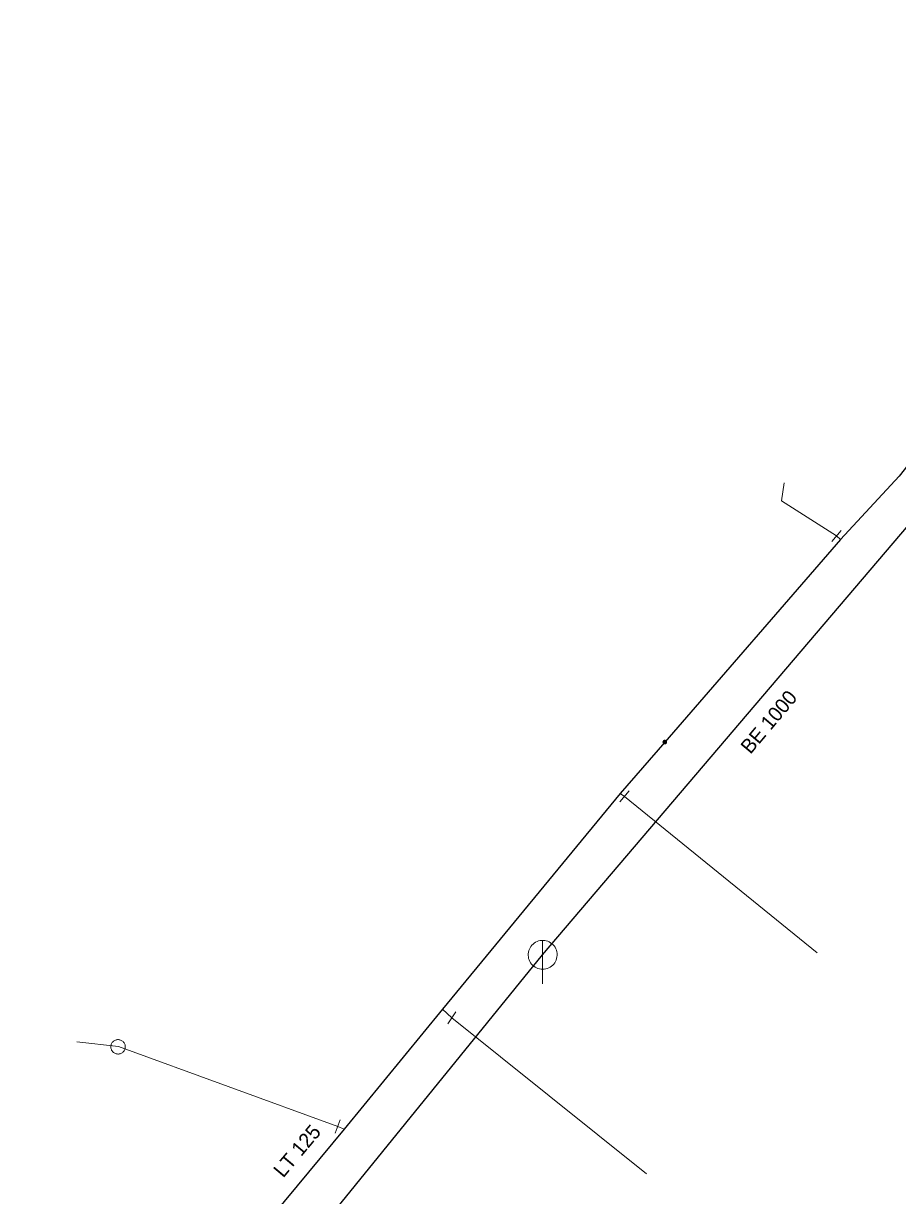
# Model space of a CAD drawing. Extents: x -791337 to -790755, y -988454 to -987923.
# Drawn here: x -791010.1 to -790949.7, y -988277.2 to -988196.2 of the extents above; entities that cross this region are included whole.
import ezdxf

# ---------------------------------------------------------------- set-up
doc = ezdxf.new("R2010")
doc.units = 0
doc.header["$LTSCALE"] = 0.4
for name, color, linetype, lineweight in [('1', 7, 'Continuous', 13), ('13', 7, 'Continuous', 13), ('14', 7, 'Continuous', 25), ('17', 7, 'Continuous', 25), ('22', 7, 'Continuous', 13), ('23', 7, 'Continuous', 13), ('34', 7, 'Continuous', 13), ('9', 7, 'Continuous', 13)]:
    doc.layers.add(name, color=color, linetype=linetype, lineweight=lineweight)

msp = doc.modelspace()

# ---------------------------------------------------------------- linework, layer by layer
at = {"layer": '13'}
for p, q in [((-790968.589, -988249.619), (-790955.254, -988260.441)), ((-790981.155, -988264.329), (-790980.511, -988264.931)), ((-790980.511, -988264.931), (-790967.056, -988275.712))]:
    msp.add_line(p, q, dxfattribs=at)
for points in [[(-790953.929, -988231.608), (-790957.739, -988229.175), (-790957.552, -988227.934)], [(-790988.399, -988272.438), (-791003.556, -988266.918), (-791006.438, -988266.59)]]:
    msp.add_lwpolyline(points, dxfattribs=at)
at = {"layer": '14'}
msp.add_line((-790974.239, -988260.57), (-790944.001, -988225.028), dxfattribs=at)
at = {"layer": '14', "lineweight": 13}
for p, q in [((-790953.649, -988231.855), (-790953.929, -988231.608)), ((-790968.875, -988249.407), (-790968.589, -988249.619)), ((-790987.956, -988272.624), (-790988.399, -988272.438))]:
    msp.add_line(p, q, dxfattribs=at)
at = {"layer": '14'}
msp.add_lwpolyline([(-791005.342, -988298.738), (-790994.723, -988285.809), (-790974.239, -988260.57)], dxfattribs=at)
at = {"layer": '17'}
for points in [[(-790868.789, -988131.909), (-790886.164, -988144.675), (-790899.148, -988162.743), (-790910.179, -988178.094), (-790927.416, -988199.874), (-790939.877, -988215.123), (-790949.601, -988227.486), (-790953.649, -988231.855), (-790965.795, -988245.864)], [(-790965.795, -988245.864), (-790968.875, -988249.407), (-790981.155, -988264.329), (-790987.956, -988272.624), (-790992.881, -988278.57), (-791010.125, -988299.302)]]:
    msp.add_lwpolyline(points, dxfattribs=at)
at = {"layer": '22'}
msp.add_line((-790974.239, -988262.57), (-790974.238, -988259.57), dxfattribs=at)
msp.add_lwpolyline([(-790973.239, -988260.57), (-790973.244, -988260.461), (-790973.262, -988260.353), (-790973.292, -988260.247), (-790973.332, -988260.146), (-790973.384, -988260.049), (-790973.446, -988259.959), (-790973.518, -988259.876), (-790973.598, -988259.802), (-790973.686, -988259.736), (-790973.78, -988259.681), (-790973.88, -988259.636), (-790973.985, -988259.603), (-790974.092, -988259.581), (-790974.201, -988259.571), (-790974.311, -988259.573), (-790974.419, -988259.587), (-790974.526, -988259.612), (-790974.629, -988259.649), (-790974.727, -988259.698), (-790974.819, -988259.756), (-790974.905, -988259.825), (-790974.982, -988259.902), (-790975.051, -988259.988), (-790975.11, -988260.08), (-790975.158, -988260.178), (-790975.195, -988260.281), (-790975.221, -988260.388), (-790975.235, -988260.496), (-790975.238, -988260.606), (-790975.228, -988260.715), (-790975.207, -988260.822), (-790975.173, -988260.926), (-790975.129, -988261.026), (-790975.074, -988261.121), (-790975.008, -988261.209), (-790974.934, -988261.289), (-790974.851, -988261.361), (-790974.761, -988261.423), (-790974.665, -988261.475), (-790974.563, -988261.516), (-790974.458, -988261.546), (-790974.35, -988261.564), (-790974.24, -988261.57), (-790974.131, -988261.564), (-790974.023, -988261.546), (-790973.918, -988261.517), (-790973.816, -988261.476), (-790973.719, -988261.424), (-790973.629, -988261.362), (-790973.546, -988261.291), (-790973.471, -988261.211), (-790973.406, -988261.123), (-790973.35, -988261.029), (-790973.306, -988260.929), (-790973.272, -988260.825), (-790973.25, -988260.717), (-790973.24, -988260.608)], close=True, dxfattribs=at)
at = {"layer": '23'}
for points in [[(-791003.116, -988267.105), (-791003.1, -988267.054), (-791003.09, -988267.002), (-791003.086, -988266.951), (-791003.087, -988266.899), (-791003.093, -988266.847), (-791003.105, -988266.795), (-791003.121, -988266.746), (-791003.143, -988266.699), (-791003.169, -988266.654), (-791003.2, -988266.612), (-791003.236, -988266.573), (-791003.276, -988266.538), (-791003.318, -988266.508), (-791003.363, -988266.483), (-791003.411, -988266.462), (-791003.462, -988266.446), (-791003.512, -988266.436), (-791003.566, -988266.431), (-791003.616, -988266.431), (-791003.669, -988266.437), (-791003.721, -988266.45), (-791003.77, -988266.466), (-791003.818, -988266.488), (-791003.863, -988266.514), (-791003.904, -988266.545), (-791003.943, -988266.582), (-791003.977, -988266.62), (-791004.007, -988266.663), (-791004.033, -988266.709), (-791004.054, -988266.757), (-791004.07, -988266.806), (-791004.08, -988266.858), (-791004.085, -988266.911), (-791004.085, -988266.962), (-791004.078, -988267.013), (-791004.066, -988267.065), (-791004.05, -988267.115), (-791004.028, -988267.163), (-791004.001, -988267.208)], [(-791003.566, -988266.431), (-791003.616, -988266.431), (-791003.669, -988266.437), (-791003.721, -988266.45), (-791003.77, -988266.466), (-791003.818, -988266.488), (-791003.863, -988266.514), (-791003.904, -988266.545), (-791003.943, -988266.582), (-791003.977, -988266.62), (-791004.007, -988266.663), (-791004.033, -988266.709), (-791004.054, -988266.757), (-791004.07, -988266.806), (-791004.08, -988266.858), (-791004.085, -988266.911), (-791004.085, -988266.962), (-791004.078, -988267.013), (-791004.066, -988267.065), (-791004.05, -988267.115), (-791004.028, -988267.163), (-791004.001, -988267.208), (-791003.971, -988267.249), (-791003.934, -988267.288), (-791003.896, -988267.323), (-791003.852, -988267.353), (-791003.807, -988267.377), (-791003.76, -988267.399), (-791003.71, -988267.414), (-791003.658, -988267.425), (-791003.606, -988267.43), (-791003.554, -988267.429), (-791003.501, -988267.423), (-791003.451, -988267.412), (-791003.401, -988267.394), (-791003.354, -988267.374), (-791003.309, -988267.347), (-791003.266, -988267.315), (-791003.227, -988267.28), (-791003.193, -988267.24)], [(-791004.001, -988267.208), (-791003.971, -988267.249), (-791003.934, -988267.288), (-791003.896, -988267.323), (-791003.852, -988267.353), (-791003.807, -988267.377), (-791003.76, -988267.399), (-791003.71, -988267.414), (-791003.658, -988267.425), (-791003.606, -988267.43), (-791003.554, -988267.429), (-791003.501, -988267.423), (-791003.451, -988267.412), (-791003.401, -988267.394), (-791003.354, -988267.374), (-791003.309, -988267.347), (-791003.266, -988267.315), (-791003.227, -988267.28), (-791003.193, -988267.24), (-791003.164, -988267.197), (-791003.138, -988267.152), (-791003.116, -988267.105), (-791003.1, -988267.054), (-791003.09, -988267.002), (-791003.086, -988266.951), (-791003.087, -988266.899), (-791003.093, -988266.847), (-791003.105, -988266.795), (-791003.121, -988266.746), (-791003.143, -988266.699), (-791003.169, -988266.654), (-791003.2, -988266.612), (-791003.236, -988266.573), (-791003.276, -988266.538), (-791003.318, -988266.508), (-791003.363, -988266.483), (-791003.411, -988266.462), (-791003.462, -988266.446), (-791003.512, -988266.436), (-791003.566, -988266.431)], [(-791003.193, -988267.24), (-791003.164, -988267.197), (-791003.138, -988267.152), (-791003.116, -988267.105)]]:
    msp.add_lwpolyline(points, dxfattribs=at)
at = {"layer": '34'}
for p, q in [((-790953.603, -988231.228), (-790954.254, -988231.987)), ((-790968.27, -988249.233), (-790968.907, -988250.004)), ((-790980.24, -988264.51), (-790980.782, -988265.35)), ((-790988.228, -988271.968), (-790988.57, -988272.907))]:
    msp.add_line(p, q, dxfattribs=at)
at = {"layer": '9'}
for points in [[(-790965.921, -988245.864), (-790965.921, -988245.877), (-790965.919, -988245.89), (-790965.916, -988245.903), (-790965.911, -988245.915), (-790965.905, -988245.927), (-790965.898, -988245.938), (-790965.89, -988245.948), (-790965.88, -988245.958), (-790965.87, -988245.966), (-790965.859, -988245.973), (-790965.847, -988245.979), (-790965.835, -988245.984), (-790965.822, -988245.987), (-790965.809, -988245.989), (-790965.796, -988245.991), (-790965.783, -988245.99), (-790965.77, -988245.988), (-790965.757, -988245.985), (-790965.745, -988245.98), (-790965.733, -988245.974), (-790965.722, -988245.967), (-790965.712, -988245.959), (-790965.702, -988245.949), (-790965.694, -988245.939), (-790965.687, -988245.928), (-790965.681, -988245.916), (-790965.676, -988245.904), (-790965.673, -988245.891), (-790965.671, -988245.878), (-790965.669, -988245.865), (-790965.67, -988245.852), (-790965.672, -988245.839), (-790965.675, -988245.826), (-790965.68, -988245.814), (-790965.686, -988245.802), (-790965.693, -988245.791), (-790965.701, -988245.781), (-790965.711, -988245.771), (-790965.721, -988245.763), (-790965.732, -988245.756), (-790965.744, -988245.75), (-790965.756, -988245.745), (-790965.769, -988245.742), (-790965.782, -988245.74), (-790965.795, -988245.739), (-790965.808, -988245.739), (-790965.821, -988245.741), (-790965.834, -988245.744), (-790965.846, -988245.749), (-790965.858, -988245.755), (-790965.869, -988245.762), (-790965.879, -988245.77), (-790965.889, -988245.78), (-790965.897, -988245.79), (-790965.904, -988245.801), (-790965.91, -988245.813), (-790965.915, -988245.825), (-790965.918, -988245.838), (-790965.92, -988245.851)], [(-790965.901, -988245.864), (-790965.902, -988245.875), (-790965.9, -988245.886), (-790965.897, -988245.897), (-790965.893, -988245.907), (-790965.888, -988245.917), (-790965.882, -988245.926), (-790965.875, -988245.935), (-790965.867, -988245.943), (-790965.858, -988245.95), (-790965.849, -988245.956), (-790965.839, -988245.961), (-790965.829, -988245.965), (-790965.818, -988245.968), (-790965.807, -988245.971), (-790965.796, -988245.971), (-790965.785, -988245.971), (-790965.774, -988245.969), (-790965.763, -988245.966), (-790965.753, -988245.962), (-790965.743, -988245.957), (-790965.734, -988245.951), (-790965.725, -988245.944), (-790965.717, -988245.936), (-790965.71, -988245.927), (-790965.704, -988245.918), (-790965.699, -988245.908), (-790965.695, -988245.898), (-790965.692, -988245.887), (-790965.69, -988245.876), (-790965.689, -988245.865), (-790965.689, -988245.854), (-790965.691, -988245.843), (-790965.694, -988245.832), (-790965.698, -988245.822), (-790965.703, -988245.812), (-790965.709, -988245.803), (-790965.716, -988245.794), (-790965.724, -988245.786), (-790965.733, -988245.779), (-790965.742, -988245.773), (-790965.752, -988245.768), (-790965.762, -988245.764), (-790965.773, -988245.761), (-790965.784, -988245.759), (-790965.795, -988245.759), (-790965.806, -988245.758), (-790965.817, -988245.76), (-790965.828, -988245.763), (-790965.838, -988245.767), (-790965.848, -988245.772), (-790965.857, -988245.778), (-790965.866, -988245.785), (-790965.874, -988245.793), (-790965.881, -988245.802), (-790965.887, -988245.811), (-790965.892, -988245.821), (-790965.896, -988245.831), (-790965.899, -988245.842), (-790965.901, -988245.853)], [(-790965.882, -988245.864), (-790965.882, -988245.873), (-790965.881, -988245.882), (-790965.878, -988245.891), (-790965.875, -988245.899), (-790965.871, -988245.907), (-790965.866, -988245.915), (-790965.86, -988245.922), (-790965.854, -988245.928), (-790965.847, -988245.934), (-790965.839, -988245.939), (-790965.831, -988245.943), (-790965.823, -988245.946), (-790965.814, -988245.949), (-790965.805, -988245.95), (-790965.796, -988245.952), (-790965.787, -988245.951), (-790965.778, -988245.95), (-790965.769, -988245.947), (-790965.761, -988245.944), (-790965.753, -988245.94), (-790965.745, -988245.935), (-790965.738, -988245.929), (-790965.732, -988245.923), (-790965.726, -988245.916), (-790965.721, -988245.908), (-790965.717, -988245.9), (-790965.714, -988245.892), (-790965.711, -988245.883), (-790965.71, -988245.874), (-790965.708, -988245.865), (-790965.709, -988245.856), (-790965.71, -988245.847), (-790965.713, -988245.838), (-790965.716, -988245.83), (-790965.72, -988245.822), (-790965.725, -988245.814), (-790965.731, -988245.807), (-790965.737, -988245.801), (-790965.744, -988245.795), (-790965.752, -988245.79), (-790965.76, -988245.786), (-790965.768, -988245.783), (-790965.777, -988245.78), (-790965.786, -988245.779), (-790965.795, -988245.778), (-790965.804, -988245.778), (-790965.813, -988245.779), (-790965.822, -988245.782), (-790965.83, -988245.785), (-790965.838, -988245.789), (-790965.846, -988245.794), (-790965.853, -988245.8), (-790965.859, -988245.806), (-790965.865, -988245.813), (-790965.87, -988245.821), (-790965.874, -988245.829), (-790965.877, -988245.837), (-790965.88, -988245.846), (-790965.881, -988245.855)], [(-790965.862, -988245.864), (-790965.862, -988245.871), (-790965.861, -988245.878), (-790965.86, -988245.885), (-790965.857, -988245.891), (-790965.854, -988245.897), (-790965.85, -988245.903), (-790965.846, -988245.909), (-790965.841, -988245.914), (-790965.835, -988245.918), (-790965.829, -988245.922), (-790965.823, -988245.925), (-790965.817, -988245.928), (-790965.81, -988245.929), (-790965.803, -988245.932), (-790965.796, -988245.932), (-790965.789, -988245.932), (-790965.782, -988245.93), (-790965.775, -988245.929), (-790965.769, -988245.926), (-790965.762, -988245.923), (-790965.757, -988245.919), (-790965.751, -988245.915), (-790965.746, -988245.91), (-790965.742, -988245.904), (-790965.738, -988245.898), (-790965.735, -988245.892), (-790965.732, -988245.886), (-790965.73, -988245.879), (-790965.729, -988245.872), (-790965.728, -988245.865), (-790965.728, -988245.858), (-790965.729, -988245.851), (-790965.731, -988245.844), (-790965.734, -988245.838), (-790965.737, -988245.831), (-790965.741, -988245.826), (-790965.745, -988245.82), (-790965.75, -988245.815), (-790965.756, -988245.811), (-790965.761, -988245.807), (-790965.768, -988245.804), (-790965.774, -988245.801), (-790965.781, -988245.799), (-790965.788, -988245.798), (-790965.795, -988245.798), (-790965.802, -988245.798), (-790965.809, -988245.798), (-790965.816, -988245.8), (-790965.822, -988245.803), (-790965.828, -988245.806), (-790965.834, -988245.81), (-790965.84, -988245.814), (-790965.845, -988245.819), (-790965.849, -988245.825), (-790965.853, -988245.83), (-790965.856, -988245.837), (-790965.859, -988245.843), (-790965.86, -988245.85), (-790965.862, -988245.857)], [(-790965.842, -988245.864), (-790965.842, -988245.869), (-790965.842, -988245.874), (-790965.841, -988245.879), (-790965.839, -988245.883), (-790965.837, -988245.888), (-790965.834, -988245.892), (-790965.831, -988245.895), (-790965.827, -988245.899), (-790965.824, -988245.902), (-790965.82, -988245.905), (-790965.815, -988245.907), (-790965.811, -988245.909), (-790965.806, -988245.91), (-790965.801, -988245.912), (-790965.796, -988245.912), (-790965.791, -988245.912), (-790965.786, -988245.911), (-790965.781, -988245.91), (-790965.777, -988245.908), (-790965.772, -988245.906), (-790965.768, -988245.903), (-790965.764, -988245.9), (-790965.761, -988245.896), (-790965.758, -988245.893), (-790965.755, -988245.889), (-790965.753, -988245.884), (-790965.751, -988245.88), (-790965.75, -988245.875), (-790965.749, -988245.87), (-790965.748, -988245.865), (-790965.748, -988245.86), (-790965.749, -988245.855), (-790965.75, -988245.85), (-790965.752, -988245.846), (-790965.754, -988245.841), (-790965.757, -988245.837), (-790965.76, -988245.833), (-790965.763, -988245.83), (-790965.767, -988245.827), (-790965.771, -988245.824), (-790965.776, -988245.822), (-790965.78, -988245.82), (-790965.785, -988245.819), (-790965.79, -988245.818), (-790965.795, -988245.818), (-790965.8, -988245.818), (-790965.805, -988245.819), (-790965.81, -988245.819), (-790965.814, -988245.821), (-790965.819, -988245.823), (-790965.823, -988245.826), (-790965.826, -988245.829), (-790965.83, -988245.832), (-790965.833, -988245.836), (-790965.836, -988245.84), (-790965.838, -988245.845), (-790965.84, -988245.849), (-790965.841, -988245.854), (-790965.842, -988245.859)], [(-790965.822, -988245.864), (-790965.822, -988245.867), (-790965.823, -988245.87), (-790965.822, -988245.872), (-790965.821, -988245.875), (-790965.82, -988245.878), (-790965.818, -988245.88), (-790965.816, -988245.882), (-790965.814, -988245.884), (-790965.812, -988245.886), (-790965.81, -988245.888), (-790965.807, -988245.89), (-790965.804, -988245.891), (-790965.802, -988245.891), (-790965.799, -988245.892), (-790965.796, -988245.892), (-790965.793, -988245.892), (-790965.79, -988245.892), (-790965.787, -988245.891), (-790965.785, -988245.89), (-790965.782, -988245.889), (-790965.78, -988245.887), (-790965.777, -988245.885), (-790965.775, -988245.883), (-790965.774, -988245.881), (-790965.772, -988245.879), (-790965.771, -988245.876), (-790965.769, -988245.873), (-790965.769, -988245.871), (-790965.768, -988245.868), (-790965.767, -988245.865), (-790965.768, -988245.862), (-790965.768, -988245.859), (-790965.769, -988245.856), (-790965.77, -988245.854), (-790965.771, -988245.851), (-790965.773, -988245.849), (-790965.774, -988245.846), (-790965.776, -988245.844), (-790965.779, -988245.843), (-790965.781, -988245.841), (-790965.784, -988245.84), (-790965.786, -988245.839), (-790965.789, -988245.838), (-790965.792, -988245.838), (-790965.795, -988245.837), (-790965.798, -988245.838), (-790965.801, -988245.837), (-790965.803, -988245.839), (-790965.806, -988245.839), (-790965.809, -988245.84), (-790965.811, -988245.842), (-790965.813, -988245.843), (-790965.815, -988245.845), (-790965.817, -988245.848), (-790965.819, -988245.85), (-790965.82, -988245.853), (-790965.821, -988245.855), (-790965.822, -988245.858), (-790965.822, -988245.861)], [(-790965.803, -988245.864), (-790965.803, -988245.866), (-790965.803, -988245.866), (-790965.802, -988245.866), (-790965.802, -988245.868), (-790965.803, -988245.869), (-790965.801, -988245.869), (-790965.801, -988245.869), (-790965.801, -988245.871), (-790965.801, -988245.871), (-790965.8, -988245.872), (-790965.798, -988245.872), (-790965.798, -988245.872), (-790965.798, -988245.873), (-790965.796, -988245.873), (-790965.796, -988245.873), (-790965.795, -988245.873), (-790965.794, -988245.873), (-790965.794, -988245.872), (-790965.793, -988245.872), (-790965.791, -988245.872), (-790965.791, -988245.871), (-790965.791, -988245.871), (-790965.79, -988245.87), (-790965.79, -988245.87), (-790965.788, -988245.869), (-790965.788, -988245.868), (-790965.787, -988245.867), (-790965.787, -988245.867), (-790965.787, -988245.866), (-790965.787, -988245.865), (-790965.787, -988245.864), (-790965.787, -988245.863), (-790965.787, -988245.863), (-790965.788, -988245.862), (-790965.788, -988245.861), (-790965.789, -988245.86), (-790965.789, -988245.86), (-790965.79, -988245.859), (-790965.79, -988245.859), (-790965.791, -988245.858), (-790965.792, -988245.858), (-790965.793, -988245.857), (-790965.793, -988245.857), (-790965.794, -988245.857), (-790965.795, -988245.857), (-790965.796, -988245.857), (-790965.797, -988245.857), (-790965.797, -988245.857), (-790965.798, -988245.858), (-790965.799, -988245.857), (-790965.8, -988245.859), (-790965.8, -988245.859), (-790965.801, -988245.859), (-790965.801, -988245.859), (-790965.802, -988245.861), (-790965.802, -988245.862), (-790965.802, -988245.863), (-790965.803, -988245.863), (-790965.803, -988245.864)]]:
    msp.add_lwpolyline(points, close=True, dxfattribs=at)

# ---------------------------------------------------------------- texts
at = {"layer": '1'}
for s, p in [('BE 1000 ', (-790959.876, -988246.75)), ('LT 125', (-790992.171, -988276.038))]:
    msp.add_text(s, height=1, rotation=50, dxfattribs=at).set_placement(p)

doc.saveas('drawing.dxf')
